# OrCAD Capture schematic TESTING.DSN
size A
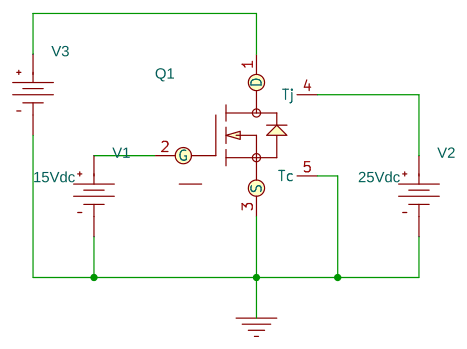
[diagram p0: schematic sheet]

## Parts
Q1  C3M0045065D
V1  VDC
V2  VDC
V3  VDC

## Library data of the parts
Q1 = C3M0045065D_v2
V1 = VDC: DC: 15Vdc
V2 = VDC: DC: 25Vdc
V3 = VDC

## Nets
0: Q1.3(S) Q1.5(Tc) V1.1(-) V2.1(-) V3.1(-)
N00171: Q1.2(G) V1.0(+)
N00202: Q1.1(D) V3.0(+)
N00217: Q1.4(Tj) V2.0(+)
